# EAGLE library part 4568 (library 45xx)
PHASE COMPARATOR/PROGRAMMABLE COUNTER
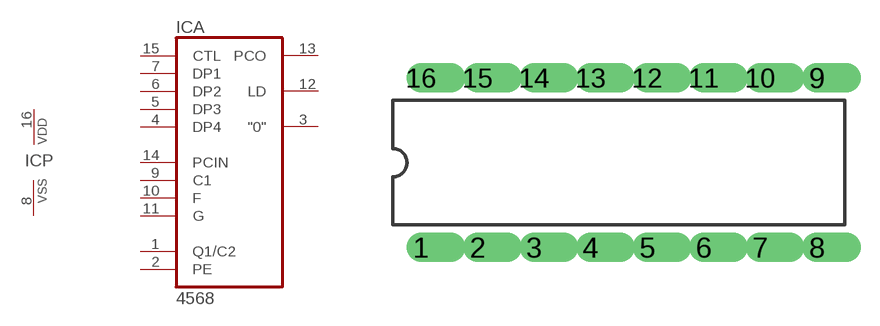
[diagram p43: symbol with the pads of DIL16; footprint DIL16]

Designator prefix IC; gates A=4568 P=PWRN

## 4568N  [DIL16]
1  A:Q1/C2
2  A:PE  in
3  A:"0"  out
4  A:DP4  in
5  A:DP3  in
6  A:DP2  in
7  A:DP1  in
8  P:VSS  pwr
9  A:C1  in
10  A:F  in
11  A:G  in
12  A:LD  out
13  A:PCO  out
14  A:PCIN  in
15  A:CTL  in
16  P:VDD  pwr

## Footprint DIL16 (pad centres in mm)
Dual In Line
drill 0.813 offset: 1 -8.89,-3.81; 2 -6.35,-3.81; 3 -3.81,-3.81; 4 -1.27,-3.81; 5 1.27,-3.81; 6 3.81,-3.81; 7 6.35,-3.81; 8 8.89,-3.81; 9 8.89,3.81; 10 6.35,3.81; 11 3.81,3.81; 12 1.27,3.81; 13 -1.27,3.81; 14 -3.81,3.81; 15 -6.35,3.81; 16 -8.89,3.81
